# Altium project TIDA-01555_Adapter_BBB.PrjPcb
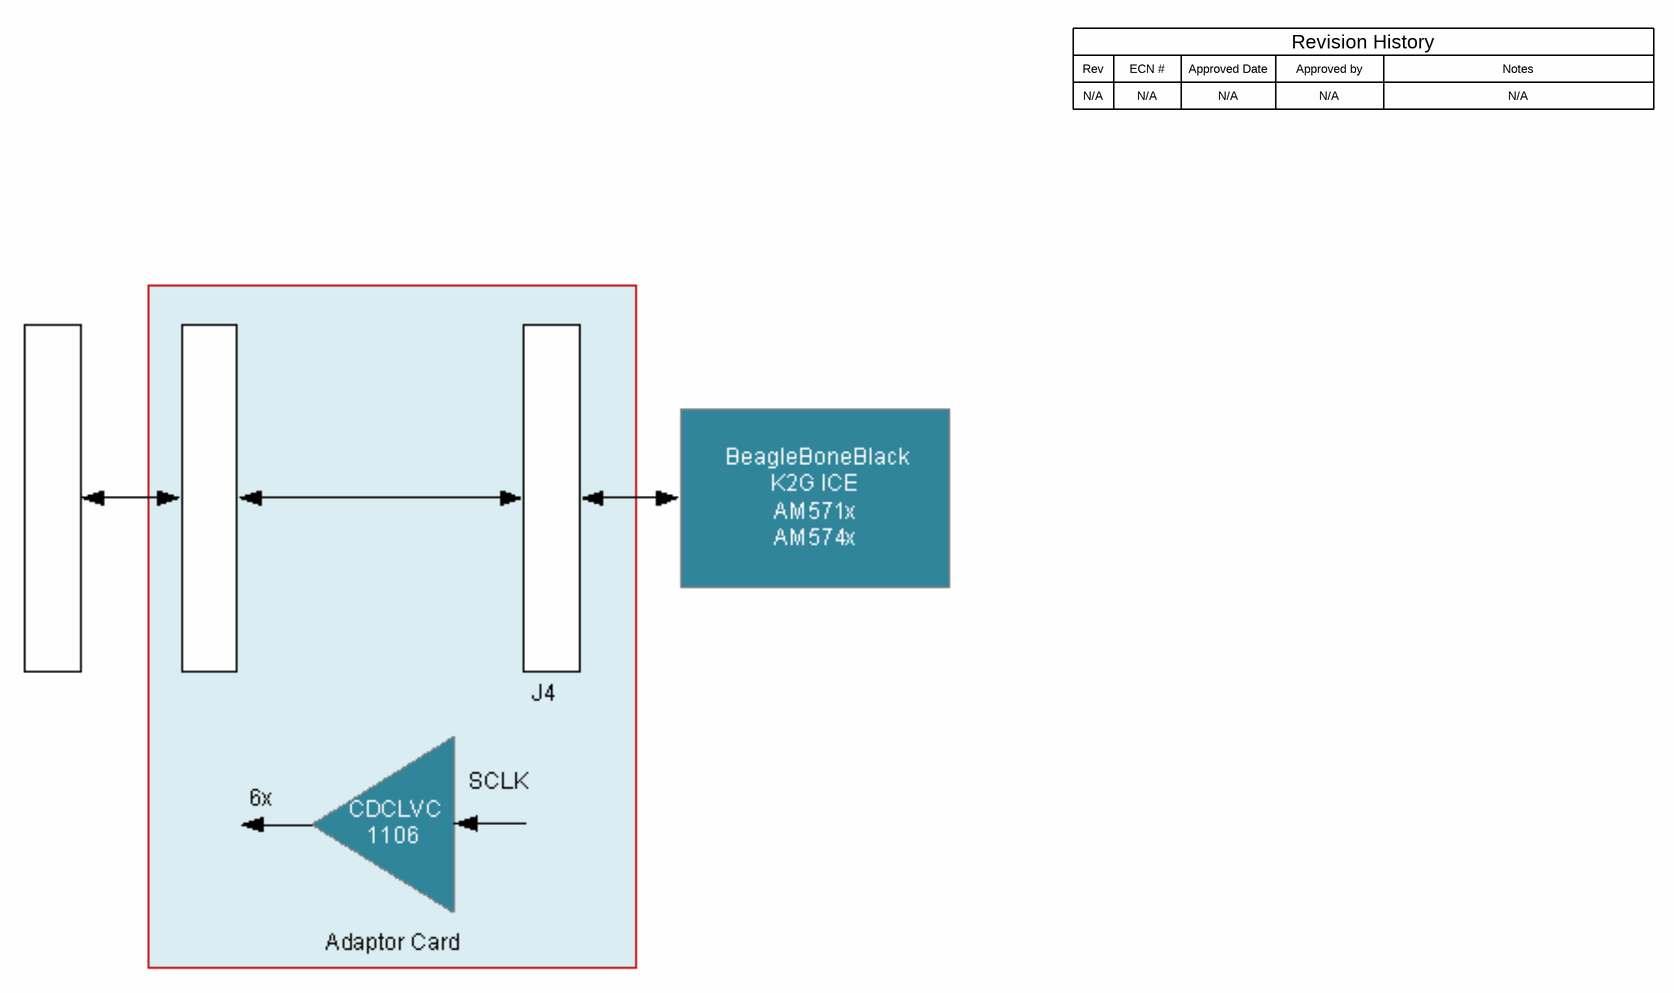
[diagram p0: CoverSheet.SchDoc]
CopyrightYear: 2017; PCB_Layout: Prasanna Rajagopal; PCB_Rev: E1; PRJ_Customer: Public Release; PRJ_Engineer: Prasanna Rajagopal; PRJ_Number: TIDA-01555-BBB; PRJ_Title: Enhanced Interface to connect multiple ADCs with Processor; SCH_Rev: E1; TechSupport: http://www.ti.com/support; TID: TIDA-01555
4 sheets, 26 parts. Net scope: global (net labels, ports and power ports of the same name join across sheets).
Board file: PCB.PcbDoc
Sheets:
  CoverSheet.SchDoc
  BlankSheet.SchDoc
  EVM_Hardware.SchDoc
  Sheet1.SchDoc

## Sheet CoverSheet.SchDoc
size 431 x 279 mm; Date: Not shown in title block; ApprovedBy: Not shown in title block; CheckedBy: Not shown in title block; Author: Not shown in title block; CompanyName: Not shown in title block; Engineer: Not shown in title block; Organization: Not shown in title block; Address1: Not shown in title block; Address2: Not shown in title block; Address3: Not shown in title block; Address4: Not shown in title block; DocumentNumber: 1; Revision: Use project parameter SCH_Rev; SheetNumber: 1; SheetTotal: 3; PageSetup: Record=PageOptions¦CenterHorizontal=True¦CenterVertical=True¦PrintScale=1.00¦XCorrection=1.00¦YCorrection=1.00¦PrintKind=0¦BorderSize=5000000¦LeftOffset=0¦BottomOffset=0¦Orientation=2¦PaperLength=1000¦PaperWidth=1000¦Scale=100¦PaperSource=15¦PrintQuality=600¦MediaType=1¦DitherType=10¦PaperKind=Letter¦PrintScaleMode=1

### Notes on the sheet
- Rev
- N/A
- ECN #
- Approved Date
- Approved by
- Revision History
- Notes

## Sheet BlankSheet.SchDoc
size 431 x 279 mm; Date: Not shown in title block; ApprovedBy: Not shown in title block; CheckedBy: Not shown in title block; Author: Not shown in title block; CompanyName: Not shown in title block; Engineer: Not shown in title block; Organization: Not shown in title block; Address1: Not shown in title block; Address2: Not shown in title block; Address3: Not shown in title block; Address4: Not shown in title block; DocumentNumber: 1; Revision: Use project parameter SCH_Rev; SheetNumber: 2; SheetTotal: 3; PageSetup: Record=PageOptions¦CenterHorizontal=True¦CenterVertical=True¦PrintScale=1.00¦XCorrection=1.00¦YCorrection=1.00¦PrintKind=0¦BorderSize=5000000¦LeftOffset=0¦BottomOffset=0¦Orientation=2¦PaperLength=1000¦PaperWidth=1000¦Scale=100¦PaperSource=15¦PrintQuality=600¦MediaType=1¦DitherType=10¦PaperKind=Letter¦PrintScaleMode=1

## Sheet EVM_Hardware.SchDoc
size 431 x 279 mm; Date: Not shown in title block; ApprovedBy: Not shown in title block; CheckedBy: Not shown in title block; Author: Not shown in title block; CompanyName: Not shown in title block; Engineer: Not shown in title block; Organization: Not shown in title block; Address1: Not shown in title block; Address2: Not shown in title block; Address3: Not shown in title block; Address4: Not shown in title block; DocumentNumber: 1; Revision: Use project parameter SCH_Rev; SheetNumber: 3; SheetTotal: 3; PageSetup: Record=PageOptions¦CenterHorizontal=True¦CenterVertical=True¦PrintScale=1.00¦XCorrection=1.00¦YCorrection=1.00¦PrintKind=0¦BorderSize=5000000¦LeftOffset=0¦BottomOffset=0¦Orientation=2¦PaperLength=1000¦PaperWidth=1000¦Scale=100¦PaperSource=15¦PrintQuality=600¦MediaType=1¦DitherType=10¦PaperKind=Letter¦PrintScaleMode=1
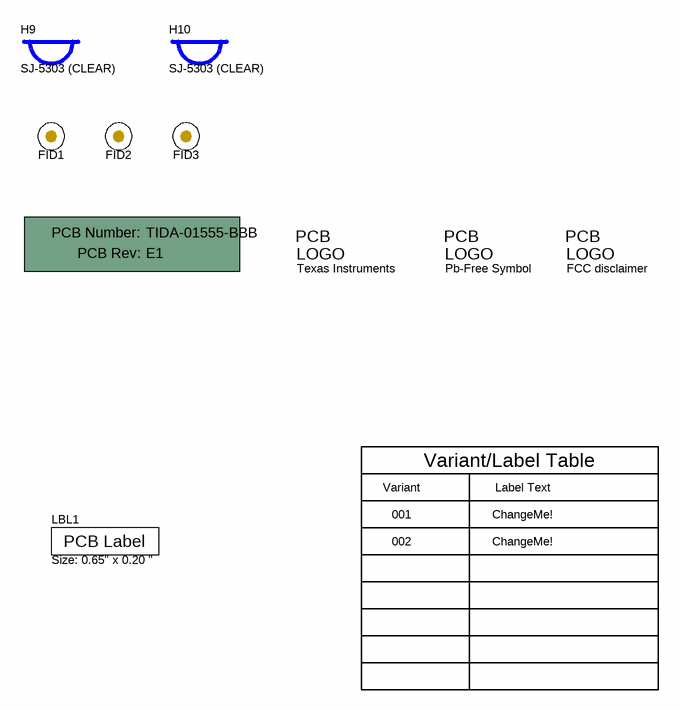
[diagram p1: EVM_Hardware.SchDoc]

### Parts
!PCB1  Printed Circuit Board  (value not drawn)  (mechanical)
FID1  Fiducial  [Fiducial10-20]  (value not drawn)
FID2  Fiducial  [Fiducial10-20]  (value not drawn)
FID3  Fiducial  [Fiducial10-20]  (value not drawn)
H9  SJ-5303 (CLEAR)  [Bumpon_SJ5003Transparent]
H10  SJ-5303 (CLEAR)  [Bumpon_SJ5003Transparent]
LBL1  Size: 0.65" x 0.20 "  [Label_650x200]
Logo1  Texas Instruments  [TI_Stacked_Overlay_Small]  (no BOM)
Logo2  Pb-Free Symbol  [Pb-Free_Overlay_Small]  (no BOM)
Logo3  FCC disclaimer  [FCC_disclaimer]  (no BOM)

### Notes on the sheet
- Variant
- Variant/Label Table
- Label Text
- 001
- 002
- ChangeMe!

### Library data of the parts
!PCB1 = PCB: Manufacturer: Any; PartNumber: TIDA-01555-BBB; SymbolCreator: a0412235
FID1-FID3 = Fiducial: Fiducial mark.  There is nothing to buy or mount.; SymbolCreator: codlsc
H9 H10 = SJ-5303 (CLEAR): Bumpon, Hemisphere, 0.44 X 0.20, Clear; Manufacturer: 3M; SymbolCreator: a0412235
LBL1 = THT-14-423-10: Thermal Transfer Printable Labels, 0.650" W x 0.200" H - 10,000 per roll; Manufacturer: Brady; SymbolCreator: a0412235; CompType: Label
Logo1 = TI_Logo: Texas Instrument Corporate Signature; SymbolCreator: codlsc
Logo2 = Pb-Free: SymbolCreator: a0412235
Logo3 = FCC_disclaimer: SymbolCreator: codlsc

## Sheet Sheet1.SchDoc
size 431 x 279 mm; Date: Not shown in title block; ApprovedBy: Not shown in title block; CheckedBy: Not shown in title block; Author: Not shown in title block; CompanyName: Not shown in title block; Engineer: Not shown in title block; Organization: Not shown in title block; Address1: Not shown in title block; Address2: Not shown in title block; Address3: Not shown in title block; Address4: Not shown in title block; DocumentNumber: 1; Revision: Use project parameter SCH_Rev; SheetNumber: 2; SheetTotal: 3; PageSetup: Record=PageOptions¦CenterHorizontal=True¦CenterVertical=True¦PrintScale=1.00¦XCorrection=1.00¦YCorrection=1.00¦PrintKind=0¦BorderSize=5000000¦LeftOffset=0¦BottomOffset=0¦Orientation=2¦PaperLength=1000¦PaperWidth=1000¦Scale=100¦PaperSource=15¦PrintQuality=600¦MediaType=1¦DitherType=10¦PaperKind=Letter¦PrintScaleMode=1
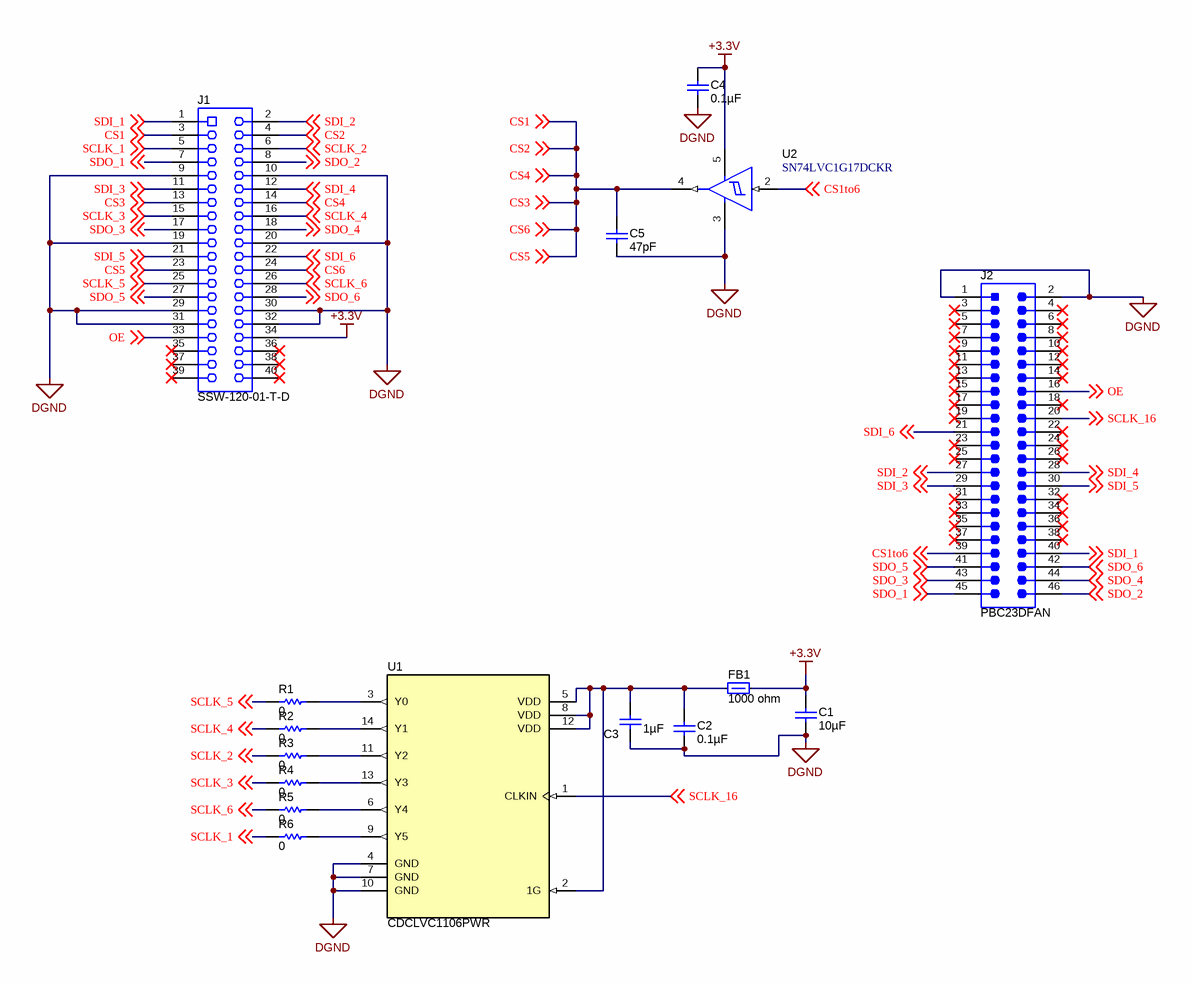
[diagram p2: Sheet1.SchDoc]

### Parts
C1  ValueDisplayed: 10µF  [1206]  (hidden comment: 885012208069)
C2  ValueDisplayed: 0.1µF  [0603]  (hidden comment: 06033C104JAT2A)
C3  ValueDisplayed: 1µF  [0603]  (hidden comment: CGA3E3X5R1H105K080AB)
C4  ValueDisplayed: 0.1µF  [0603]  (hidden comment: GRM188R71C104KA01D)
C5  ValueDisplayed: 47pF  [0402]  (hidden comment: GRM1555C1E470JA01D)
FB1  value 1000 ohm  [MMZ1608_095]  (hidden comment: MMZ1608B102CTA00)
J1  SSW-120-01-T-D  [Samtec_SSW-120-01-x-D]
J2  PBC23DFAN  [Sullins_PBC23DFAN]
R1  ValueDisplayed: 0  [0402]  (hidden comment: CRCW04020000Z0ED)
R2  ValueDisplayed: 0  [0402]  (hidden comment: CRCW04020000Z0ED)
R3  ValueDisplayed: 0  [0402]  (hidden comment: CRCW04020000Z0ED)
R4  ValueDisplayed: 0  [0402]  (hidden comment: CRCW04020000Z0ED)
R5  ValueDisplayed: 0  [0402]  (hidden comment: CRCW04020000Z0ED)
R6  ValueDisplayed: 0  [0402]  (hidden comment: CRCW04020000Z0ED)
U1  CDCLVC1106PWR  [PW0014A_N]
U2  SN74LVC1G17DCKR  [DCK0005A_N]

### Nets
+3.3V: C1.1 C4.1 FB1.2 J1.34 U2.5(VCC)
DGND: C1.2 C2.2 C3.2 C4.2 C5.2 J1.9 J1.10 J1.19 J1.20 J1.29 J1.30 J1.31 J1.32 J2.1 J2.2 U1.4(GND) U1.7(GND) U1.10(GND) U2.3(GND)
CS1: C5.1 J1.3 J1.4 J1.13 J1.14 J1.23 J1.24 U2.4(Y) ; off-sheet CS1, off-sheet CS2, off-sheet CS3, off-sheet CS4, off-sheet CS5, off-sheet CS6  [also labelled CS2, CS3, CS4, CS5, CS6]
CS1to6: J2.39 U2.2(A) ; off-sheet CS1to6
OE: J1.33 J2.16 ; off-sheet OE
SCLK_1: J1.5 R6.1 ; off-sheet SCLK_1
SCLK_2: J1.6 R3.1 ; off-sheet SCLK_2
SCLK_3: J1.15 R4.1 ; off-sheet SCLK_3
SCLK_4: J1.16 R2.1 ; off-sheet SCLK_4
SCLK_5: J1.25 R1.1 ; off-sheet SCLK_5
SCLK_6: J1.26 R5.1 ; off-sheet SCLK_6
SCLK_16: J2.20 U1.1(CLKIN) ; off-sheet SCLK_16
SDI_1: J1.1 J2.40 ; off-sheet SDI_1
SDI_2: J1.2 J2.27 ; off-sheet SDI_2
SDI_3: J1.11 J2.29 ; off-sheet SDI_3
SDI_4: J1.12 J2.28 ; off-sheet SDI_4
SDI_5: J1.21 J2.30 ; off-sheet SDI_5
SDI_6: J1.22 J2.21 ; off-sheet SDI_6
SDO_1: J1.7 J2.45 ; off-sheet SDO_1
SDO_2: J1.8 J2.46 ; off-sheet SDO_2
SDO_3: J1.17 J2.43 ; off-sheet SDO_3
SDO_4: J1.18 J2.44 ; off-sheet SDO_4
SDO_5: J1.27 J2.41 ; off-sheet SDO_5
SDO_6: J1.28 J2.42 ; off-sheet SDO_6
NetC2_1: C2.1 C3.1 FB1.1 U1.2(1G) U1.5(VDD) U1.8(VDD) U1.12(VDD)
NetR1_2: R1.2 U1.3(Y0)
NetR2_2: R2.2 U1.14(Y1)
NetR3_2: R3.2 U1.11(Y2)
NetR4_2: R4.2 U1.13(Y3)
NetR5_2: R5.2 U1.6(Y4)
NetR6_2: R6.2 U1.9(Y5)

Not connected (* = marked no-connect by the designer): J1 35* 36* 37* 38* 39* 40*; J2 3* 4* 5* 6* 7* 8* 9* 10* 11* 12* 13* 14* 15* 17* 18* 19* 22* 23* 24* 25* 26* 31* 32* 33* 34* 35* 36* 37* 38*

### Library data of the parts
C1 = GRM31CR71E106KA12L: CAP, CERM, 10uF, 25V, +/-10%, X7R, 1206; Manufacturer: Wurth; Polarized: N; CompType: Capacitor; U/M: EA; Cap_F: 0.00001; Tolerance_%: 10; Value1: Unknown; VDC_V: 25; TaMin_C: -55; TaMax_C: 125; Cap_Case: 2220
C2 = 06033C104JAT2A: CAP, CERM, 0.1uF, 25V, +/-5%, X7R, 0603; Manufacturer: AVX; Polarized: N; CompType: Capacitor; U/M: EA; Cap_F: 0.0000001; Tolerance_%: 5; ESR_Ohm: 0.05; Value1: 0.05 ohm; VDC_V: 25; TaMin_C: -55; TaMax_C: 125
C3 = GRM188R61H105KAALD: CAP, CERM, 1uF, 50V, +/-10%, X5R, 0603; Manufacturer: TDK; Polarized: N; CompType: Capacitor; U/M: EA; Cap_F: 0.000001; Tolerance_%: 10; Value1: Unknown; VDC_V: 50; TaMin_C: -55; TaMax_C: 85
C4 = GRM188R71C104KA01D: CAP, CERM, 0.1 µF, 16 V, +/- 10%, X7R, 0603; Manufacturer: MuRata; Polarized: N; CompType: Capacitor; Value: 0.1uF; U/M: EA; Cap_F: 0.0000001; Tolerance_%: 10; Value1: Unknown; VDC_V: 16; Value2: 16V; TaMin_C: -55; TaMax_C: 125; SizeArea_mm2: 1.28; SizeAreaWB_mm2: 4.68; SizeX_mm: 1.6; SizeY_mm: 0.8; SizeZ_mm: 1; AEC Category: Q200
C5 = GRM1555C1E470JA01D: CAP, CERM, 47 pF, 25 V,+/- 5%, C0G/NP0, 0402; Manufacturer: MuRata; Polarized: N; CompType: Capacitor; Value: 47pF; U/M: EA; Cap_F: 0.000000000047; Tolerance_%: 5; VDC_V: 25; Value2: 25V; TaMin_C: -55; TaMax_C: 125; SizeArea_mm2: 0.5; SizeAreaWB_mm2: 3; SizeX_mm: 1; SizeZ_mm: 0.6; AEC Category: Q200; Green_Lifecycle: Active; Green_REACh: Passed
FB1 = MMZ1608B102CTA00: Ferrite Bead, 1000 ohm @ 100 MHz, 0.3 A, 0603; Manufacturer: TDK; Imax_A: 0.3; DCR_ohm: 0.6; Value1: 0.6 ohm; Value2: 0.3A; ZTyp@100MHz_Ohm: 1000
J1 = SSW-120-01-T-D: Receptacle, 2.54mm, 2x20, TH; Manufacturer: Samtec; SymbolCreator: a0412235; CompType: Socket Strip
J2 = PBC23DFAN: Header, 100 mil, 23x2, Gold, TH; Manufacturer: Sullins Connector Solutions; SymbolCreator: Altium; Pitch_mm: 2.54; Gender: Male; Shrouded: N; Row_Count: 2; Current_A: 3; Voltage_V: 1800; Cert_UL: Y
R1-R6 = CRCW04020000Z0ED: RES, 0, 5%, 0.063 W, 0402; Manufacturer: Vishay-Dale; CompType: Resistor; Value: 0; Value_Code: 0000; Tolerance_%: 5; Power_W: 0.063; Value2: 0.063W; VDC_V: 50; TempCo: 200 ppm/C; EIA_Code: E24; U/M: EA; SizeArea_mm2: 0.5; SizeX_mm: 1; SizeZ_mm: 0.6; AEC Category: Q200; Green_Lifecycle: Active; Green_REACh: Passed
U1 = CDCLVC1106PWR: Low Jitter, 1:6 LVCMOS Fan-out Clock Buffer, PW0014A (TSSOP-14); Manufacturer: Texas Instruments; SymbolCreator: Altium; SizeArea_mm2: 32; SizeAreaWB_mm2: 58.8; SizeX_mm: 6.4; SizeY_mm: 5; SizeZ_mm: 1.2; CompType: IC; U/M: EA; Green_Lifecycle: Active; Green_REACh: Passed
U2 = SN74LVC1G17DCKR: SINGLE SCHMITT-TRIGGER BUFFER, DCK0005A (SOT-SC70-5); Alternate PartNumber: SN74LVC1G17DCKT; Manufacturer: Texas Instruments; SymbolCreator: a0799628; SizeArea_mm2: 4.2; SizeAreaWB_mm2: 9.3; SizeX_mm: 2.1; SizeY_mm: 2; SizeZ_mm: 1.1; CompType: IC; U/M: EA

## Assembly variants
001: not fitted FID1 FID2 FID3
